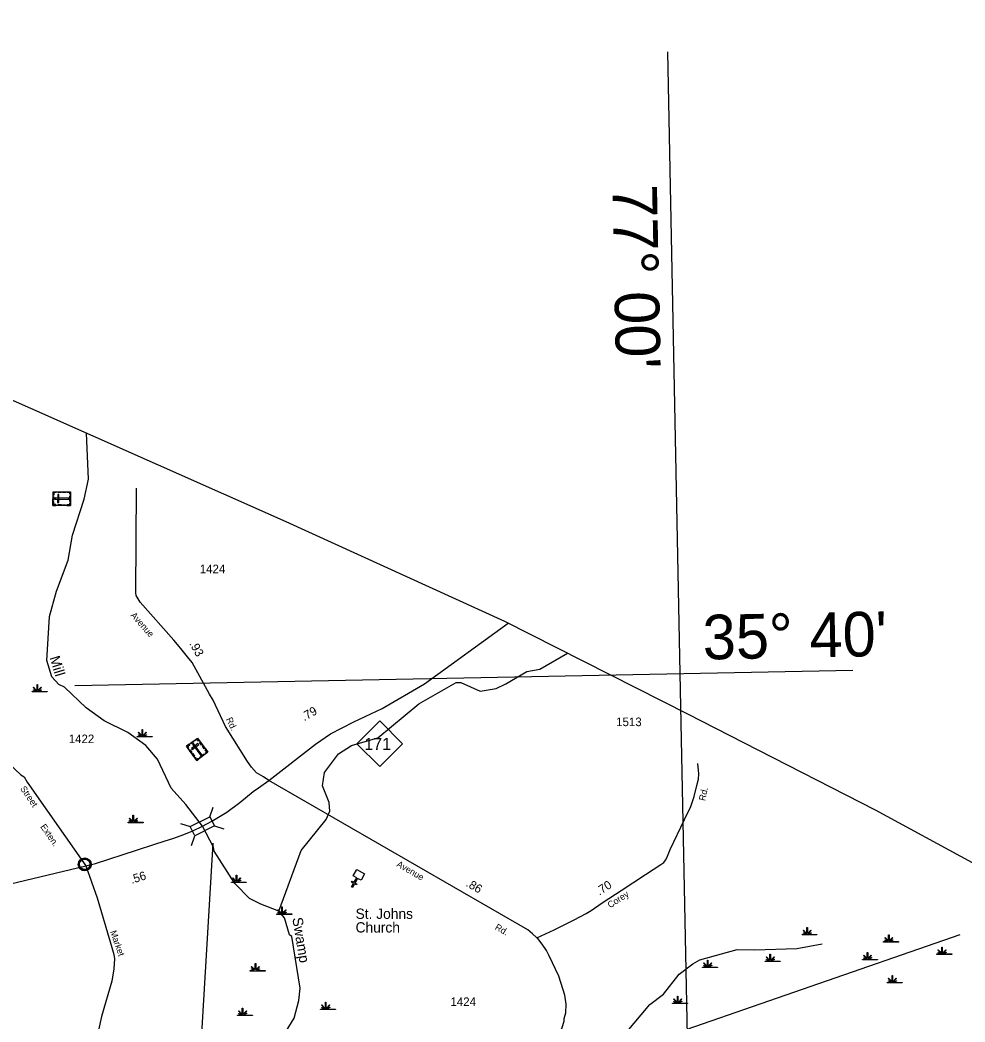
# Model space of a CAD drawing. Extents: x 2532689 to 2764727, y 536648 to 732970.
# Drawn here: x 2584380 to 2598153, y 698470 to 713074 of the extents above; entities that cross this region are included whole.
import ezdxf

# ---------------------------------------------------------------- set-up
doc = ezdxf.new("R2010")
doc.units = 0
for name, color, linetype in [('Exist Boundary Political CountyLine', 7, 'Continuous'), ('Exist Civil Demographics Community CELL', 7, 'Continuous'), ('Exist Cultural Cemetery CELL', 7, 'Continuous'), ('Exist Cultural Church CELL', 7, 'Continuous'), ('Exist Cultural Church Label', 7, 'Continuous'), ('Exist Hydrographic Creek Single Shore', 7, 'Continuous'), ('Exist Hydrographic Swamp CELL', 7, 'Continuous'), ('Exist Hydrographic Swamp Label', 7, 'Continuous'), ('Exist Road Primary NC Attributed', 7, 'Continuous'), ('Exist Road Primary NC Mileage Hundredths English Label', 7, 'Continuous'), ('Exist Road Primary NC Shield CELL', 7, 'Continuous'), ('Exist Road Primary NC Shield Number Label', 7, 'Continuous'), ('Exist Road Primary NC Structure Standard Bridge CELL', 7, 'Continuous'), ('Exist Road Primary NC Structure Standard Bridge Number Label', 7, 'Continuous'), ('Exist Road Secondary Mileage Hundredths English Label', 7, 'Continuous'), ('Exist Road Secondary Structure Standard Bridge Number Label', 7, 'Continuous'), ('Exist Road Secondary Type 20 Attributed', 7, 'Continuous'), ('Exist Road Secondary Type 51 Attributed', 7, 'Continuous'), ('Exist Road Secondary Type 51 Label', 7, 'Continuous'), ('Exist Road Secondary Type 51 Number Label', 7, 'Continuous'), ('Map Preparation Longitude Latitude Label', 7, 'Continuous'), ('Map Preparation Longitude Latitude Lines', 7, 'Continuous')]:
    doc.layers.add(name, color=color, linetype=linetype)

msp = doc.modelspace()

# ---------------------------------------------------------------- linework, layer by layer
at = {"layer": 'Exist Boundary Political CountyLine'}
for points in [[(2594930, 702539), (2594125, 702951), (2591448, 704307), (2588259, 705761), (2583625, 707815), (2577241, 711578), (2574077, 712998), (2571328, 714581), (2560378, 720855), (2555265, 723493), (2546974, 728176), (2544857, 729105)], [(2596850, 701558), (2594930, 702539)], [(2598265, 700789), (2596850, 701558)]]:
    msp.add_lwpolyline(points, dxfattribs=at)
at = {"layer": 'Exist Civil Demographics Community CELL'}
msp.add_lwpolyline([(2585245, 700780), (2585246, 700785), (2585248, 700792), (2585251, 700799), (2585254, 700805), (2585257, 700811), (2585261, 700816), (2585265, 700820), (2585270, 700825), (2585275, 700829), (2585281, 700833), (2585286, 700836), (2585291, 700838), (2585296, 700841), (2585302, 700842), (2585306, 700843), (2585311, 700844), (2585315, 700845), (2585321, 700845), (2585326, 700845), (2585331, 700845), (2585336, 700844), (2585341, 700843), (2585346, 700842), (2585351, 700840), (2585358, 700837), (2585364, 700833), (2585369, 700830), (2585375, 700826), (2585378, 700823), (2585382, 700818), (2585386, 700814), (2585389, 700809), (2585392, 700804), (2585395, 700799), (2585397, 700794), (2585398, 700789), (2585399, 700784), (2585401, 700778), (2585401, 700773), (2585401, 700767), (2585401, 700762), (2585401, 700756), (2585400, 700751), (2585398, 700744), (2585396, 700739), (2585394, 700733), (2585391, 700727), (2585387, 700722), (2585384, 700717), (2585380, 700713), (2585375, 700708), (2585370, 700704), (2585365, 700700), (2585360, 700698), (2585353, 700694), (2585346, 700692), (2585340, 700690), (2585334, 700689), (2585329, 700688), (2585325, 700688), (2585319, 700688), (2585315, 700689), (2585309, 700689), (2585303, 700691), (2585299, 700692), (2585294, 700694), (2585289, 700696), (2585285, 700698), (2585278, 700702), (2585273, 700706), (2585268, 700711), (2585263, 700716), (2585260, 700720), (2585257, 700724), (2585253, 700731), (2585251, 700735), (2585250, 700739), (2585247, 700747), (2585245, 700754), (2585245, 700759), (2585244, 700765), (2585244, 700770), (2585245, 700776)], close=True, dxfattribs=at)
for centre, radius in [((2585323, 700767), 94.3), ((2585323, 700768), 76.7)]:
    msp.add_circle(centre, radius, dxfattribs=at)
at = {"layer": 'Exist Cultural Cemetery CELL'}
for points in [[(2584860, 706000), (2584862, 706199), (2585116, 706197), (2585115, 705998)], [(2584905, 706199), (2584905, 706188), (2584873, 706188), (2584872, 706147), (2584861, 706148), (2584862, 706199)], [(2584861, 706074), (2584861, 706126), (2584872, 706126), (2584872, 706074)], [(2584890, 706109), (2584890, 706090), (2585093, 706089), (2585093, 706107)], [(2584928, 706041), (2584947, 706040), (2584948, 706158), (2584929, 706158)], [(2584978, 706187), (2584935, 706187), (2584935, 706199), (2584978, 706198)], [(2585044, 706187), (2585001, 706187), (2585001, 706198), (2585044, 706198)], [(2585116, 706164), (2585104, 706164), (2585105, 706186), (2585064, 706187), (2585064, 706198), (2585116, 706197)], [(2585104, 706056), (2585104, 706141), (2585116, 706141), (2585115, 706056)], [(2584903, 706000), (2584903, 706011), (2584871, 706012), (2584872, 706052), (2584860, 706052), (2584860, 706000)], [(2584977, 705999), (2584934, 706000), (2584934, 706011), (2584978, 706011)], [(2585045, 705999), (2585001, 705999), (2585001, 706010), (2585045, 706010)], [(2585115, 706031), (2585103, 706031), (2585103, 706009), (2585063, 706010), (2585063, 705999), (2585115, 705998)], [(2586805, 702488), (2586965, 702606), (2587117, 702402), (2586957, 702283)], [(2586991, 702572), (2586982, 702565), (2586962, 702591), (2586930, 702567), (2586923, 702575), (2586965, 702606)], [(2586831, 702453), (2586840, 702460), (2586821, 702486), (2586853, 702510), (2586847, 702519), (2586805, 702488)], [(2586875, 702393), (2586849, 702428), (2586858, 702435), (2586884, 702400)], [(2586864, 702532), (2586906, 702563), (2586913, 702554), (2586871, 702523)], [(2586878, 702457), (2586889, 702442), (2586984, 702513), (2586973, 702528)], [(2586910, 702529), (2586895, 702518), (2587016, 702355), (2587031, 702366)], [(2587025, 702506), (2586999, 702541), (2587008, 702548), (2587034, 702513)], [(2587064, 702453), (2587039, 702488), (2587048, 702495), (2587073, 702460)], [(2587090, 702382), (2587083, 702391), (2587101, 702405), (2587077, 702437), (2587086, 702444), (2587117, 702402)], [(2586915, 702339), (2586889, 702374), (2586898, 702381), (2586924, 702346)], [(2586983, 702303), (2586976, 702312), (2586959, 702299), (2586935, 702332), (2586926, 702325), (2586957, 702283)], [(2586996, 702327), (2587064, 702377), (2587071, 702368), (2587003, 702318)]]:
    msp.add_lwpolyline(points, close=True, dxfattribs=at)
at = {"layer": 'Exist Cultural Church CELL'}
msp.add_lwpolyline([(2589350, 700535), (2589301, 700563), (2589263, 700498), (2589290, 700481), (2589282, 700468), (2589255, 700484), (2589224, 700432), (2589210, 700440), (2589241, 700492), (2589213, 700508), (2589221, 700522), (2589249, 700506), (2589287, 700571), (2589237, 700600), (2589290, 700693), (2589403, 700627)], close=True, dxfattribs=at)
at = {"layer": 'Exist Hydrographic Creek Single Shore'}
for points in [[(2588152, 700085), (2587891, 700189), (2587723, 700268), (2587510, 700489), (2587209, 700959), (2587200, 701018), (2587039, 701325), (2586796, 701642), (2586583, 701880), (2586383, 702302), (2586213, 702498), (2585950, 702691), (2585605, 702861), (2585343, 703047), (2585028, 703350), (2584945, 703389), (2584842, 703503), (2584772, 703737), (2584808, 704378), (2584910, 704747), (2585084, 705201), (2585143, 705567), (2585317, 706090), (2585377, 706381), (2585349, 707051)], [(2588152, 700085), (2588476, 700968), (2588842, 701423), (2588898, 701543), (2588887, 701668), (2588791, 701913), (2588820, 702108), (2589023, 702379), (2589213, 702498), (2589594, 702612), (2590193, 703109), (2590737, 703420), (2590803, 703420), (2591089, 703293), (2591322, 703332), (2591462, 703400), (2591767, 703580), (2591958, 703611), (2592361, 703845)], [(2588180, 698211), (2588374, 698525), (2588444, 698783), (2588465, 698965), (2588342, 699715), (2588308, 699740), (2588237, 699987), (2588152, 700085)], [(2594185, 699318), (2594287, 699378), (2594834, 699525), (2595084, 699522), (2595700, 699540), (2596074, 699608)], [(2591894, 696651), (2592065, 696864), (2592309, 697209), (2593204, 698300), (2593562, 698725), (2593759, 698877), (2593987, 699166), (2594185, 699318)]]:
    msp.add_lwpolyline(points, dxfattribs=at)
at = {"layer": 'Exist Hydrographic Swamp CELL'}
for points in [[(2584557, 703287), (2584609, 703287), (2584611, 703291), (2584573, 703306), (2584576, 703311), (2584614, 703295), (2584615, 703298), (2584571, 703343), (2584576, 703348), (2584621, 703302), (2584628, 703305), (2584628, 703388), (2584635, 703388), (2584635, 703305), (2584641, 703302), (2584686, 703348), (2584692, 703343), (2584647, 703298), (2584649, 703294), (2584690, 703313), (2584692, 703308), (2584652, 703290), (2584653, 703287), (2584774, 703287), (2584774, 703280), (2584557, 703280)], [(2586088, 702632), (2586141, 702632), (2586143, 702635), (2586105, 702650), (2586108, 702655), (2586145, 702639), (2586147, 702642), (2586103, 702687), (2586108, 702692), (2586153, 702647), (2586159, 702649), (2586159, 702732), (2586167, 702732), (2586167, 702649), (2586173, 702647), (2586218, 702692), (2586223, 702687), (2586179, 702642), (2586181, 702639), (2586222, 702657), (2586224, 702652), (2586183, 702635), (2586185, 702632), (2586306, 702632), (2586306, 702624), (2586088, 702624)], [(2585955, 701381), (2586008, 701381), (2586010, 701385), (2585972, 701400), (2585975, 701405), (2586012, 701389), (2586014, 701392), (2585970, 701437), (2585975, 701442), (2586020, 701396), (2586026, 701399), (2586026, 701482), (2586034, 701482), (2586034, 701399), (2586040, 701396), (2586085, 701442), (2586090, 701437), (2586046, 701392), (2586048, 701389), (2586089, 701407), (2586091, 701402), (2586050, 701384), (2586052, 701381), (2586173, 701381), (2586173, 701374), (2585955, 701374)], [(2587461, 700509), (2587513, 700509), (2587515, 700513), (2587477, 700528), (2587480, 700533), (2587518, 700517), (2587519, 700520), (2587475, 700564), (2587480, 700570), (2587525, 700524), (2587532, 700526), (2587532, 700610), (2587539, 700610), (2587539, 700526), (2587545, 700524), (2587591, 700570), (2587596, 700564), (2587551, 700520), (2587553, 700516), (2587594, 700535), (2587597, 700530), (2587556, 700512), (2587557, 700509), (2587678, 700509), (2587678, 700502), (2587461, 700502)], [(2588123, 700045), (2588176, 700045), (2588178, 700049), (2588140, 700064), (2588143, 700069), (2588180, 700053), (2588182, 700056), (2588138, 700101), (2588143, 700106), (2588188, 700060), (2588194, 700063), (2588194, 700146), (2588202, 700146), (2588202, 700063), (2588208, 700060), (2588253, 700106), (2588258, 700101), (2588214, 700056), (2588216, 700052), (2588257, 700071), (2588259, 700066), (2588218, 700048), (2588220, 700045), (2588341, 700045), (2588341, 700038), (2588123, 700038)], [(2595779, 699745), (2595831, 699746), (2595833, 699749), (2595795, 699764), (2595798, 699769), (2595836, 699753), (2595837, 699756), (2595793, 699801), (2595798, 699806), (2595843, 699760), (2595849, 699763), (2595849, 699846), (2595857, 699846), (2595857, 699763), (2595863, 699760), (2595908, 699806), (2595913, 699801), (2595869, 699756), (2595871, 699753), (2595912, 699771), (2595914, 699766), (2595873, 699748), (2595875, 699746), (2595996, 699745), (2595996, 699738), (2595779, 699738)], [(2596968, 699642), (2597021, 699642), (2597023, 699646), (2596985, 699660), (2596988, 699666), (2597025, 699650), (2597027, 699653), (2596983, 699697), (2596988, 699702), (2597033, 699657), (2597039, 699659), (2597039, 699742), (2597047, 699742), (2597047, 699659), (2597053, 699657), (2597098, 699702), (2597103, 699697), (2597059, 699653), (2597061, 699649), (2597102, 699668), (2597104, 699663), (2597063, 699645), (2597065, 699642), (2597186, 699642), (2597186, 699635), (2596968, 699635)], [(2597744, 699461), (2597797, 699461), (2597799, 699464), (2597761, 699479), (2597764, 699484), (2597801, 699469), (2597803, 699472), (2597759, 699516), (2597764, 699521), (2597809, 699476), (2597815, 699478), (2597815, 699561), (2597823, 699561), (2597823, 699478), (2597829, 699476), (2597874, 699521), (2597879, 699516), (2597835, 699472), (2597837, 699468), (2597878, 699487), (2597880, 699482), (2597839, 699464), (2597841, 699461), (2597962, 699461), (2597962, 699454), (2597744, 699454)], [(2594329, 699271), (2594381, 699271), (2594383, 699274), (2594345, 699289), (2594348, 699294), (2594386, 699278), (2594387, 699281), (2594343, 699326), (2594348, 699331), (2594393, 699286), (2594400, 699288), (2594400, 699371), (2594407, 699371), (2594407, 699288), (2594413, 699286), (2594458, 699331), (2594464, 699326), (2594419, 699281), (2594421, 699278), (2594462, 699296), (2594464, 699291), (2594423, 699274), (2594425, 699271), (2594546, 699271), (2594546, 699263), (2594329, 699263)], [(2595240, 699358), (2595293, 699358), (2595295, 699362), (2595256, 699376), (2595259, 699382), (2595297, 699366), (2595299, 699369), (2595254, 699413), (2595259, 699418), (2595305, 699373), (2595311, 699375), (2595311, 699458), (2595318, 699458), (2595318, 699375), (2595325, 699373), (2595370, 699418), (2595375, 699413), (2595331, 699369), (2595333, 699365), (2595373, 699384), (2595376, 699379), (2595335, 699361), (2595337, 699358), (2595458, 699358), (2595458, 699351), (2595240, 699351)], [(2596658, 699383), (2596711, 699383), (2596713, 699387), (2596674, 699402), (2596677, 699407), (2596715, 699391), (2596717, 699394), (2596672, 699438), (2596677, 699444), (2596723, 699398), (2596729, 699400), (2596729, 699484), (2596736, 699484), (2596736, 699400), (2596743, 699398), (2596788, 699444), (2596793, 699438), (2596749, 699394), (2596751, 699390), (2596791, 699409), (2596794, 699404), (2596753, 699386), (2596754, 699383), (2596876, 699383), (2596876, 699376), (2596658, 699376)], [(2587736, 699221), (2587789, 699221), (2587791, 699224), (2587753, 699239), (2587756, 699244), (2587793, 699229), (2587795, 699231), (2587751, 699276), (2587756, 699281), (2587801, 699236), (2587807, 699238), (2587807, 699321), (2587815, 699321), (2587815, 699238), (2587821, 699236), (2587866, 699281), (2587871, 699276), (2587827, 699231), (2587829, 699228), (2587870, 699246), (2587872, 699241), (2587831, 699224), (2587833, 699221), (2587954, 699221), (2587954, 699213), (2587736, 699213)], [(2597020, 699047), (2597073, 699047), (2597075, 699050), (2597037, 699065), (2597039, 699070), (2597077, 699055), (2597079, 699057), (2597034, 699102), (2597039, 699107), (2597085, 699062), (2597091, 699064), (2597091, 699147), (2597098, 699147), (2597098, 699064), (2597105, 699062), (2597150, 699107), (2597155, 699102), (2597111, 699057), (2597113, 699054), (2597154, 699072), (2597156, 699067), (2597115, 699050), (2597117, 699047), (2597238, 699047), (2597238, 699039), (2597020, 699039)], [(2593892, 698746), (2593944, 698746), (2593946, 698749), (2593908, 698764), (2593911, 698769), (2593949, 698754), (2593950, 698757), (2593906, 698801), (2593911, 698806), (2593956, 698761), (2593963, 698763), (2593963, 698846), (2593970, 698846), (2593970, 698763), (2593976, 698761), (2594021, 698806), (2594027, 698801), (2593982, 698757), (2593984, 698753), (2594025, 698772), (2594027, 698767), (2593986, 698749), (2593988, 698746), (2594109, 698746), (2594109, 698739), (2593892, 698739)], [(2587549, 698571), (2587602, 698571), (2587604, 698575), (2587566, 698589), (2587568, 698595), (2587606, 698579), (2587608, 698582), (2587563, 698626), (2587568, 698631), (2587614, 698586), (2587620, 698588), (2587620, 698671), (2587627, 698671), (2587627, 698588), (2587634, 698586), (2587679, 698631), (2587684, 698626), (2587640, 698582), (2587642, 698578), (2587683, 698597), (2587685, 698592), (2587644, 698574), (2587646, 698571), (2587767, 698571), (2587767, 698564), (2587549, 698564)], [(2588760, 698658), (2588813, 698658), (2588815, 698662), (2588777, 698677), (2588779, 698682), (2588817, 698666), (2588819, 698669), (2588774, 698714), (2588780, 698719), (2588825, 698673), (2588831, 698676), (2588831, 698759), (2588838, 698759), (2588838, 698676), (2588845, 698673), (2588890, 698719), (2588895, 698714), (2588851, 698669), (2588853, 698666), (2588894, 698684), (2588896, 698679), (2588855, 698661), (2588857, 698658), (2588978, 698658), (2588978, 698651), (2588760, 698651)]]:
    msp.add_lwpolyline(points, close=True, dxfattribs=at)
at = {"layer": 'Exist Road Primary NC Attributed'}
for points in [[(2588007, 701988), (2588685, 702517), (2588907, 702669), (2589246, 702843), (2589656, 703040), (2590275, 703397), (2591494, 704284)], [(2587039, 701325), (2587174, 701397), (2587393, 701528), (2587585, 701667), (2587779, 701831), (2587858, 701883), (2588007, 701988)], [(2585341, 700746), (2585481, 700779), (2586080, 700975), (2586347, 701061), (2586480, 701104), (2586621, 701151), (2586769, 701204), (2586898, 701254), (2587039, 701325)], [(2582895, 699750), (2582935, 699777), (2583105, 699899), (2583780, 700317), (2583889, 700388), (2584013, 700432), (2585341, 700746)]]:
    msp.add_lwpolyline(points, dxfattribs=at)
at = {"layer": 'Exist Road Primary NC Shield CELL'}
msp.add_lwpolyline([(2589289, 702526), (2589622, 702859), (2589955, 702526), (2589622, 702193)], close=True, dxfattribs=at)
at = {"layer": 'Exist Road Primary NC Structure Standard Bridge CELL'}
for p, q in [((2587147, 701461), (2587194, 701601)), ((2586719, 701364), (2586859, 701318)), ((2587213, 701330), (2587353, 701283)), ((2586880, 701044), (2586926, 701183))]:
    msp.add_line(p, q, dxfattribs=at)
msp.add_lwpolyline([(2586859, 701318), (2587147, 701462), (2587214, 701327), (2586926, 701183)], close=True, dxfattribs=at)
at = {"layer": 'Exist Road Primary NC Structure Standard Bridge Number Label'}
msp.add_line((2587190, 701076), (2586635, 691831), dxfattribs=at)
at = {"layer": 'Exist Road Secondary Structure Standard Bridge Number Label'}
msp.add_lwpolyline([(2592501, 697329), (2593487, 698152), (2598084, 699743)], dxfattribs=at)
at = {"layer": 'Exist Road Secondary Type 20 Attributed'}
msp.add_lwpolyline([(2591914, 699697), (2592165, 699811), (2592458, 699961), (2592633, 700053), (2592704, 700095), (2592753, 700127), (2592881, 700216), (2593142, 700385), (2593496, 700619), (2593718, 700764), (2593762, 700796), (2593790, 700829), (2593808, 700862), (2593858, 700985), (2594066, 701422), (2594156, 701612), (2594204, 701756), (2594243, 701918), (2594270, 702010), (2594275, 702088), (2594259, 702238)], dxfattribs=at)
at = {"layer": 'Exist Road Secondary Type 51 Attributed'}
for points in [[(2588007, 701988), (2587929, 702043), (2587828, 702100), (2587752, 702185), (2587695, 702265), (2587376, 702776), (2587193, 703162), (2587141, 703249), (2586890, 703709), (2586822, 703793), (2586726, 703915), (2586624, 704035), (2586129, 704590), (2586075, 704685), (2586066, 704725), (2586078, 706251)], [(2583343, 703051), (2583379, 703022), (2584392, 702071), (2584438, 702041), (2584484, 701966), (2585341, 700746)], [(2591914, 699697), (2591907, 699703), (2591849, 699757), (2591781, 699812), (2588007, 701988)], [(2585341, 700746), (2585504, 700278), (2585719, 699555), (2585749, 699452), (2585756, 699392), (2585747, 699246), (2585717, 699065), (2585567, 698548), (2585481, 698151), (2585455, 697926), (2585434, 697677), (2585429, 697577), (2585421, 697399)], [(2591865, 697517), (2591962, 697701), (2592210, 698212), (2592283, 698389), (2592309, 698480), (2592312, 698520), (2592336, 698604), (2592340, 698729), (2592323, 698860), (2592232, 699137), (2592093, 699434), (2592052, 699513), (2591992, 699604), (2591925, 699686), (2591914, 699697)]]:
    msp.add_lwpolyline(points, dxfattribs=at)
at = {"layer": 'Map Preparation Longitude Latitude Lines'}
msp.add_line((2585181, 703375), (2596519, 703598), dxfattribs=at)
msp.add_lwpolyline([(2594139, 696821), (2594003, 703549), (2593821, 712611)], dxfattribs=at)

# ---------------------------------------------------------------- texts
at = {"layer": 'Exist Cultural Church Label'}
for s, p in [('St. Johns', (2589271, 699973)), ('Church', (2589271, 699774))]:
    msp.add_text(s, height=150, dxfattribs=at).set_placement(p)
at = {"layer": 'Exist Hydrographic Swamp Label'}
for s, rotation, p in [('Mill', 286.901, (2584810, 703781)), ('Swamp', 279.3143, (2588348, 699983))]:
    msp.add_text(s, height=150, rotation=rotation, dxfattribs=at).set_placement(p)
at = {"layer": 'Exist Road Primary NC Mileage Hundredths English Label'}
for s, rotation, p in [('.79', 30.0184, (2588523, 702852)), ('.56', 17.7986, (2586009, 700482))]:
    msp.add_text(s, height=125, rotation=rotation, dxfattribs=at).set_placement(p)
at = {"layer": 'Exist Road Primary NC Shield Number Label'}
msp.add_text('171', height=175, dxfattribs=at).set_placement((2589398, 702436))
at = {"layer": 'Exist Road Secondary Mileage Hundredths English Label'}
for s, rotation, p in [('.93', 298.6621, (2586845, 703985)), ('.86', 329.8945, (2590869, 700456)), ('.70', 33.0777, (2592824, 700310))]:
    msp.add_text(s, height=125, rotation=rotation, dxfattribs=at).set_placement(p)
at = {"layer": 'Exist Road Secondary Type 51 Label'}
for s, rotation, p in [('Avenue', 311.7323, (2585985, 704392)), ('Rd.', 295.7247, (2587379, 702883)), ('Street', 304.551, (2584377, 701870)), ('Rd.', 76.8322, (2594364, 701687)), ('Exten.', 304.551, (2584671, 701315)), ('Avenue', 329.8945, (2589860, 700743)), ('Corey', 33.0777, (2592981, 700125)), ('Market', 289.2285, (2585691, 699786)), ('Rd.', 329.8945, (2591293, 699825))]:
    msp.add_text(s, height=95, rotation=rotation, dxfattribs=at).set_placement(p)
at = {"layer": 'Exist Road Secondary Type 51 Number Label'}
for s, p in [('1424', (2587000, 705011)), ('1513', (2593069, 702782)), ('1422', (2585090, 702534)), ('1424', (2590654, 698703))]:
    msp.add_text(s, height=125, dxfattribs=at).set_placement(p)
at = {"layer": 'Map Preparation Longitude Latitude Label'}
for s, rotation, p in [("77° 00'", 271.1544, (2593013, 710671)), ("35° 40'", 1.1303, (2594336, 703752))]:
    msp.add_text(s, height=650, rotation=rotation, dxfattribs=at).set_placement(p)

doc.saveas('drawing.dxf')
